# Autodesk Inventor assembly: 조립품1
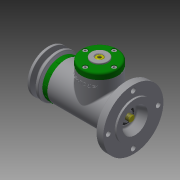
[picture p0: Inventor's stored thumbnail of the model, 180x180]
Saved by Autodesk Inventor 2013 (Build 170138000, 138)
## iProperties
Created: 2016-08
Part Number: 조립품1
Document SubType Name: Assembly
Designer: Administrator
Author: Administrator
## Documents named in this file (25)
- C:\Users\Administrator\Desktop\460808V1017\조립품1.iam
- C:\Users\Administrator\Desktop\460808V1017\본체1.ipt
- C:\Users\Administrator\Desktop\460808V1017\V-벨트풀리.ipt
- C:\Users\Administrator\Desktop\460808V1017\너트 M10.ipt
- C:\Users\Administrator\Desktop\460808V1017\링크.ipt
- C:\Users\Administrator\Desktop\460808V1017\멈춤링 15 x 1.ipt
- C:\Users\Administrator\Desktop\460808V1017\멈춤링 35x1.6.ipt
- C:\Users\Administrator\Desktop\460808V1017\베어링 15 x 35 x 11.ipt
- C:\Users\Administrator\Desktop\460808V1017\볼트 M4 x 10.ipt
- C:\Users\Administrator\Desktop\460808V1017\볼트 M4 x 12.ipt
- C:\Users\Administrator\Desktop\460808V1017\부시1.ipt
- C:\Users\Administrator\Desktop\460808V1017\부시2.ipt
- C:\Users\Administrator\Desktop\460808V1017\분할핀 1.6 x 12.ipt
- C:\Users\Administrator\Desktop\460808V1017\사이드 커버.ipt
- 사이드 커버.ipt
- C:\Users\Administrator\Desktop\460808V1017\슬라이더.ipt
- C:\Users\Administrator\Desktop\460808V1017\오일 실 15 25 7.ipt
- C:\Users\Administrator\Desktop\460808V1017\와셔 4x16.ipt
- C:\Users\Administrator\Desktop\460808V1017\와셔 10x21.ipt
- C:\Users\Administrator\Desktop\460808V1017\클래스터 핀 6 x 24.ipt
- C:\Users\Administrator\Desktop\460808V1017\키 4 x 4 x 18.ipt
- C:\Users\Administrator\Desktop\460808V1017\탑 부시.ipt
- C:\Users\Administrator\Desktop\460808V1017\탑 커버.ipt
- 탑 커버.ipt
- C:\Users\Administrator\Desktop\460808V1017\편심축.ipt
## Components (6 placed, 3 different names)
1. V-벨트풀리:1
2. ISO 4017 M4 x 10:1
3. ISO 4762 M4 x 12:1 — 각도:1
4. ISO 4762 M4 x 12:2
5. ISO 4762 M4 x 12:3
6. ISO 4762 M4 x 12:4
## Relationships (1: Angle 1)
- 각도:1 [Angle]: ISO 4762 M4 x 12:1
